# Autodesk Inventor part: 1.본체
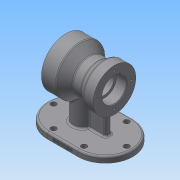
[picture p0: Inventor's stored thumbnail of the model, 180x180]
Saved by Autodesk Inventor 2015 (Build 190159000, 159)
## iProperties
Created: 2020-01
Part Number: 1.본체
Material: 일반
Document SubType Name: Modeling
Designer: user
Density: 1 g/cm^3
Appearance: 기본값
Author: user
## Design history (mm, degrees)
sketch "스케치1"
  geometry: L1 (-40, 0)-(40, 0); L2 (-40, 26)-(-40, 40); L3 (-40, 40)-(-16, 40); L4 (-16, 40)-(-1.103, 27.5); L5 (-1.103, 27.5)-(13.289, 27.5); L6 (13.289, 27.5)-(24, 35); L7 (24, 35)-(40, 35); L8 (40, 35)-(40, 20); L9 (-40, 26)-(-20, 26); L10 (-20, 26)-(-20, 16); L11 (-20, 16)-(23, 16); L12 (23, 16)-(23, 20); L13 (23, 20)-(40, 20); 2 further points
  constraints: 26 end point, 7 perpendicular, 2 parallel, 2 vertical alignment, 1 coincident, 1 horizontal, 1 midpoint, 1 vertical
  dimensions: "d4" = 35 deg angle of L5 L6; "d5" = 40 deg angle of L4 L5; "d6" = 24 distance of L2.end L3.end; "d7" = 16 distance of L6.end L7.end; "d8" = 80 distance between parallel lines of L8 L2; "d9" = 80 diameter of L3 L1; "d10" = 55 diameter of L5 L1; "d11" = 70 diameter of L7 L1; "d12" = 20 distance of L2.start L9.end; "d14" = 52 diameter of L9 L1; "d15" = 32 diameter of L11 L1; "d16" = 40 diameter of L13 L1; "d17" = 17 distance of L8.end L12.end
revolve "회전1" sketch "스케치1" stored, may be unused: angle "d18" = 90 deg
node "작업 평면1"
sketch "스케치2"
  geometry: L1 (25, 0)-(-25, 0); L2 (25, 45)-(-25, 45); L3 (-25, -45)-(25, -45); A1 r 45 centre (25, 0) between (25, -45) and (25, 45); A2 r 45 centre (-25, 0) between (-25, 45) and (-25, -45); 1 further point
  constraints: 8 end point, 4 point on circle, 4 tangent, 2 centre point, 1 horizontal, 1 midpoint, 1 parallel
  dimensions: "d20" = 50 distance of L1.start L1.end; "d21" = 45 radius of A1
extrude "돌출1" join sketch "스케치2" distance "d22" = 10; taper "d23" = 0 deg
sketch "스케치3"
  geometry: L1 (-70, 0)-(-12, 0); C1 r 16 at (-12, 0); A1 r 45 centre (-25, 0) between (-25, 45) and (-25, -45) reference; 1 further point
  constraints: 2 end point, 1 centre point, 1 coincident, 1 horizontal, 1 point on circle
  dimensions: "d24" = 58 distance of L1.start L1.end; "d25" = 32 diameter of C1
extrude "돌출2" join sketch "스케치3" stored distance "d26" = 10; taper "d27" = 0 deg
sketch "스케치4" dims "d28" = 55
  geometry: C1 r 35 at (0, 0) reference; C2 r 20 at (0, 0) reference; 2 further points
  constraints: 2 vertical alignment, 1 coincident, 2 other
hole "구멍1" sketch "스케치4" at (0, 27.5) diameter "d29" = 3.242; stored, may be unused: countersink angle "d33" = 90 deg, drill point angle "d35" = 118 deg; dims "d30" = 9, "d31" = 4, "d32" = 2, "d34" = 11
sketch "스케치5"
  geometry: L1 (40, -35)-(40, 35) reference; L2 (24, -35)-(40, -35) reference; L3 (25, -70)-(-25, -70) reference; L4 (70, -70)-(25, -70) reference; L5 (30, -35)-(30, -70); 1 further point
  constraints: 2 end point, 2 point on line, 1 perpendicular
  dimensions: "d39" = 10 distance between parallel lines of L1 L5
feature "리브1" sketch "스케치5" dims "d40" = 1, "d41" = 10, "d42" = 0, "d43" = 0, "d44" = 1, "d45" = 1
sketch "스케치6"
  geometry: L1 (3.199, 5)-(30, 5) reference; L2 (-25, -45)-(25, -45) reference; L3 (-25, 0)-(25, 0); L4 (-25, -35)-(25, -35); L5 (25, 35)-(-25, 35); A1 r 45 centre (25, 0) between (25, -45) and (25, 45) reference; A2 r 35 centre (-25, 0) between (-25, 35) and (-25, -35); A3 r 35 centre (25, 0) between (25, -35) and (25, 35); 7 further points
  constraints: 8 end point, 7 point on circle, 4 tangent, 3 coincident, 2 centre point, 2 parallel, 1 midpoint
  dimensions: "d46" = 10 distance between parallel lines of L2 L4
hole "구멍2" sketch "스케치6" at (-60, 0), (60, 0), (25, -35), (25, 35), (-25, -35), (-25, 35) diameter "d47" = 9; stored, may be unused: countersink angle "d51" = 90 deg, drill point angle "d53" = 118 deg; dims "d48" = 8.608, "d49" = 4, "d50" = 2, "d52" = 15.664
sketch "스케치7" dims "d54" = 66
  geometry: C1 r 26 at (0, 0) reference; C2 r 40 at (0, 0) reference; 2 further points
  constraints: 2 horizontal alignment, 1 coincident, 2 other
hole "구멍3" sketch "스케치7" at (-33, 0) diameter "d55" = 3.242; stored, may be unused: countersink angle "d59" = 90 deg, drill point angle "d61" = 118 deg; dims "d56" = 9, "d57" = 4, "d58" = 2, "d60" = 11
fillet "모깎기1" dims "d65" = 0.3
fillet "모깎기2" dims "d66" = 3
fillet "모깎기3" dims "d67" = 3
fillet "모깎기4" dims "d68" = 3
chamfer "모따기1" distance "d69" = 1; stored, may be unused: second distance "d70" = 2, angle "d71" = 45 deg
chamfer "모따기2" distance "d72" = 1; stored, may be unused: second distance "d73" = 2, angle "d74" = 45 deg
node "작업 평면2"
sketch "스케치8"
  geometry: L1 (95, 0)-(50, 0) reference; L2 (-45, 0)-(-45, 7) reference; 2 further points
  constraints: 1 other
  dimensions: "d76" = 4 distance from line of L1 point (25, 4); "d77" = 70 distance from line of point (25, 4) L2
feature "엠보싱1" sketch "스케치8" dims "d20" = 50, "d21" = 45, "d78" = 0.5, "d79" = 0
node "솔리드1"
pattern_circular "원형 패턴1" dims angle "d37" = 360 deg
pattern_circular "원형 패턴2" dims angle "d63" = 360 deg
other parameters: "d75" = 11.75
